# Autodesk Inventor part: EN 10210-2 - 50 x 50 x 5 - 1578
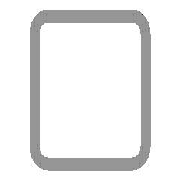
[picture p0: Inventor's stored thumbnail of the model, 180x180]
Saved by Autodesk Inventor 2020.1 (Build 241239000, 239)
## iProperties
IsCustomPart: 1
_CCFamilyMember: 16
_CCFamilyDisplayName: DIN EN 10210-2 (USAS B17.1 quadratisch) - Rohrleitung — In Klammern angegebene Größen wurden aufgehoben
_FrameMemberDoc: Frame Member File
_Version: 15.0.0
_GetPNFromCC: 1
Created: 2019-01
Part Number: EN 10210-2 - 50 x 50 x 5 - 1578
Material: Stahl, weich
Description: Rohrleitung
Document SubType Name: Modeling
Standard: DIN
Designer: lutzd
Standard Revision: 2006-07
Standards Organization: DIN
Language: de-DE
Size Designation: 50 x 50 x 5
Categories: <MemberInstance><Categories><Category DisplayName="Profile" InternalName="089c4875-fa83-4c05-b084-43b9cc11f5ed" Mnemonic="GRDR"><CategoryParameter DisplayName="
Stock Number: 50 x 50 x 5
Mass: 10816.3 g
Surface Area: 5359.62 cm^2
Volume: 1377.87 cm^3
Density: 7.85 g/cm^3
Appearance: Semi-Polished(8)
G_L: 1578,000 mm
G_W: 50,000 mm
G_H: 50,000 mm
DocNumber: ADSK-014304
Folder: .
Dimensions: 50x50x1578 mm
Mass: 10,816 kg
Title: Profil-Bauteil
Author: lutzd
Revision Number: -
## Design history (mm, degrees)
node "Startebene"
node "Endebene"
sketch "Skizze"
  geometry: L1 (-25, -17.5)-(-25, 17.5); L2 (-17.5, 25)-(17.5, 25); L3 (25, 17.5)-(25, -17.5); L4 (17.5, -25)-(-17.5, -25); L5 (-15, 20)-(15, 20); L6 (20, 15)-(20, -15); L7 (15, -20)-(-15, -20); L8 (-20, -15)-(-20, 15); L9 (0, 37.175)-(0, -37.175) reference; L10 (-37.175, 0)-(37.175, 0) reference; A1 r 7.5 centre (-17.5, -17.5) between (-25, -17.5) and (-17.5, -25); A2 r 7.5 centre (-17.5, 17.5) between (-17.5, 25) and (-25, 17.5); A3 r 7.5 centre (17.5, 17.5) between (25, 17.5) and (17.5, 25); A4 r 7.5 centre (17.5, -17.5) between (17.5, -25) and (25, -17.5); A5 r 5 centre (-15, -15) between (-20, -15) and (-15, -20); A6 r 5 centre (-15, 15) between (-15, 20) and (-20, 15); A7 r 5 centre (15, 15) between (20, 15) and (15, 20); A8 r 5 centre (15, -15) between (15, -20) and (20, -15)
  constraints: 16 end point, 16 point on circle, 16 tangent, 8 centre point, 6 equal radius, 4 parallel, 2 perpendicular, 2 other
  dimensions: "d7" = 7.5 radius of A1 (= G_IR); "d10" = 50 distance between parallel lines of L2 L4 (= G_H); "d11" = 50 distance between parallel lines of L1 L3 (= G_W); "d12" = 5 distance between parallel lines of L3 L6 (= G_T); "d15" = 25 distance between parallel lines of L2 L10 (= 0.5 x d10); "d16" = 25 distance between parallel lines of L9 L3 (= 0.5 x d11); "d19" = 5 radius of A5 (= G_T); "d20" = 5 distance between parallel lines of L4 L7 (= G_T)
extrude "Körper" new body sketch "Skizze" stored distance "d3" = 1578 (= G_L); taper "d4" = 0 deg
node "Driven Length"
  sketch "Sketch3"
    geometry: L1 (0, 0)-(10, 0) reference
    constraints: 2 end point, 1 horizontal
  workplane "Work Plane3"
  sketch "Sketch4"
    geometry: L1 (-2, 0)-(12, 0) reference; L2 (-2, 1578)-(12, 1578) reference
    dimensions: "d18" = 1578 distance between parallel lines of L1 L2 (derived)
body "Solid1"
other parameters: "G_W" = 50 [user parameter; used in 1 equation term], "G_H" = 50 [user parameter; used in 1 equation term], "G_T" = 5 [user parameter; used in 3 equation terms], "G_IR" = 7.5 [user parameter; used in 1 equation term], "G_L" = 1578 (= d18) [user parameter; used in 1 equation term], "G_OFFSET_START" = 0 [user parameter; used in 1 equation term], "G_OFFSET_END" = 203 [user parameter; used in 1 equation term], "d13" = 0 (computed from G_OFFSET_START), "d14" = 1578 (= G_OFFSET_END + B_L), "B_L" = 1375 [user parameter; used in 1 equation term], "d17" = 90 deg
